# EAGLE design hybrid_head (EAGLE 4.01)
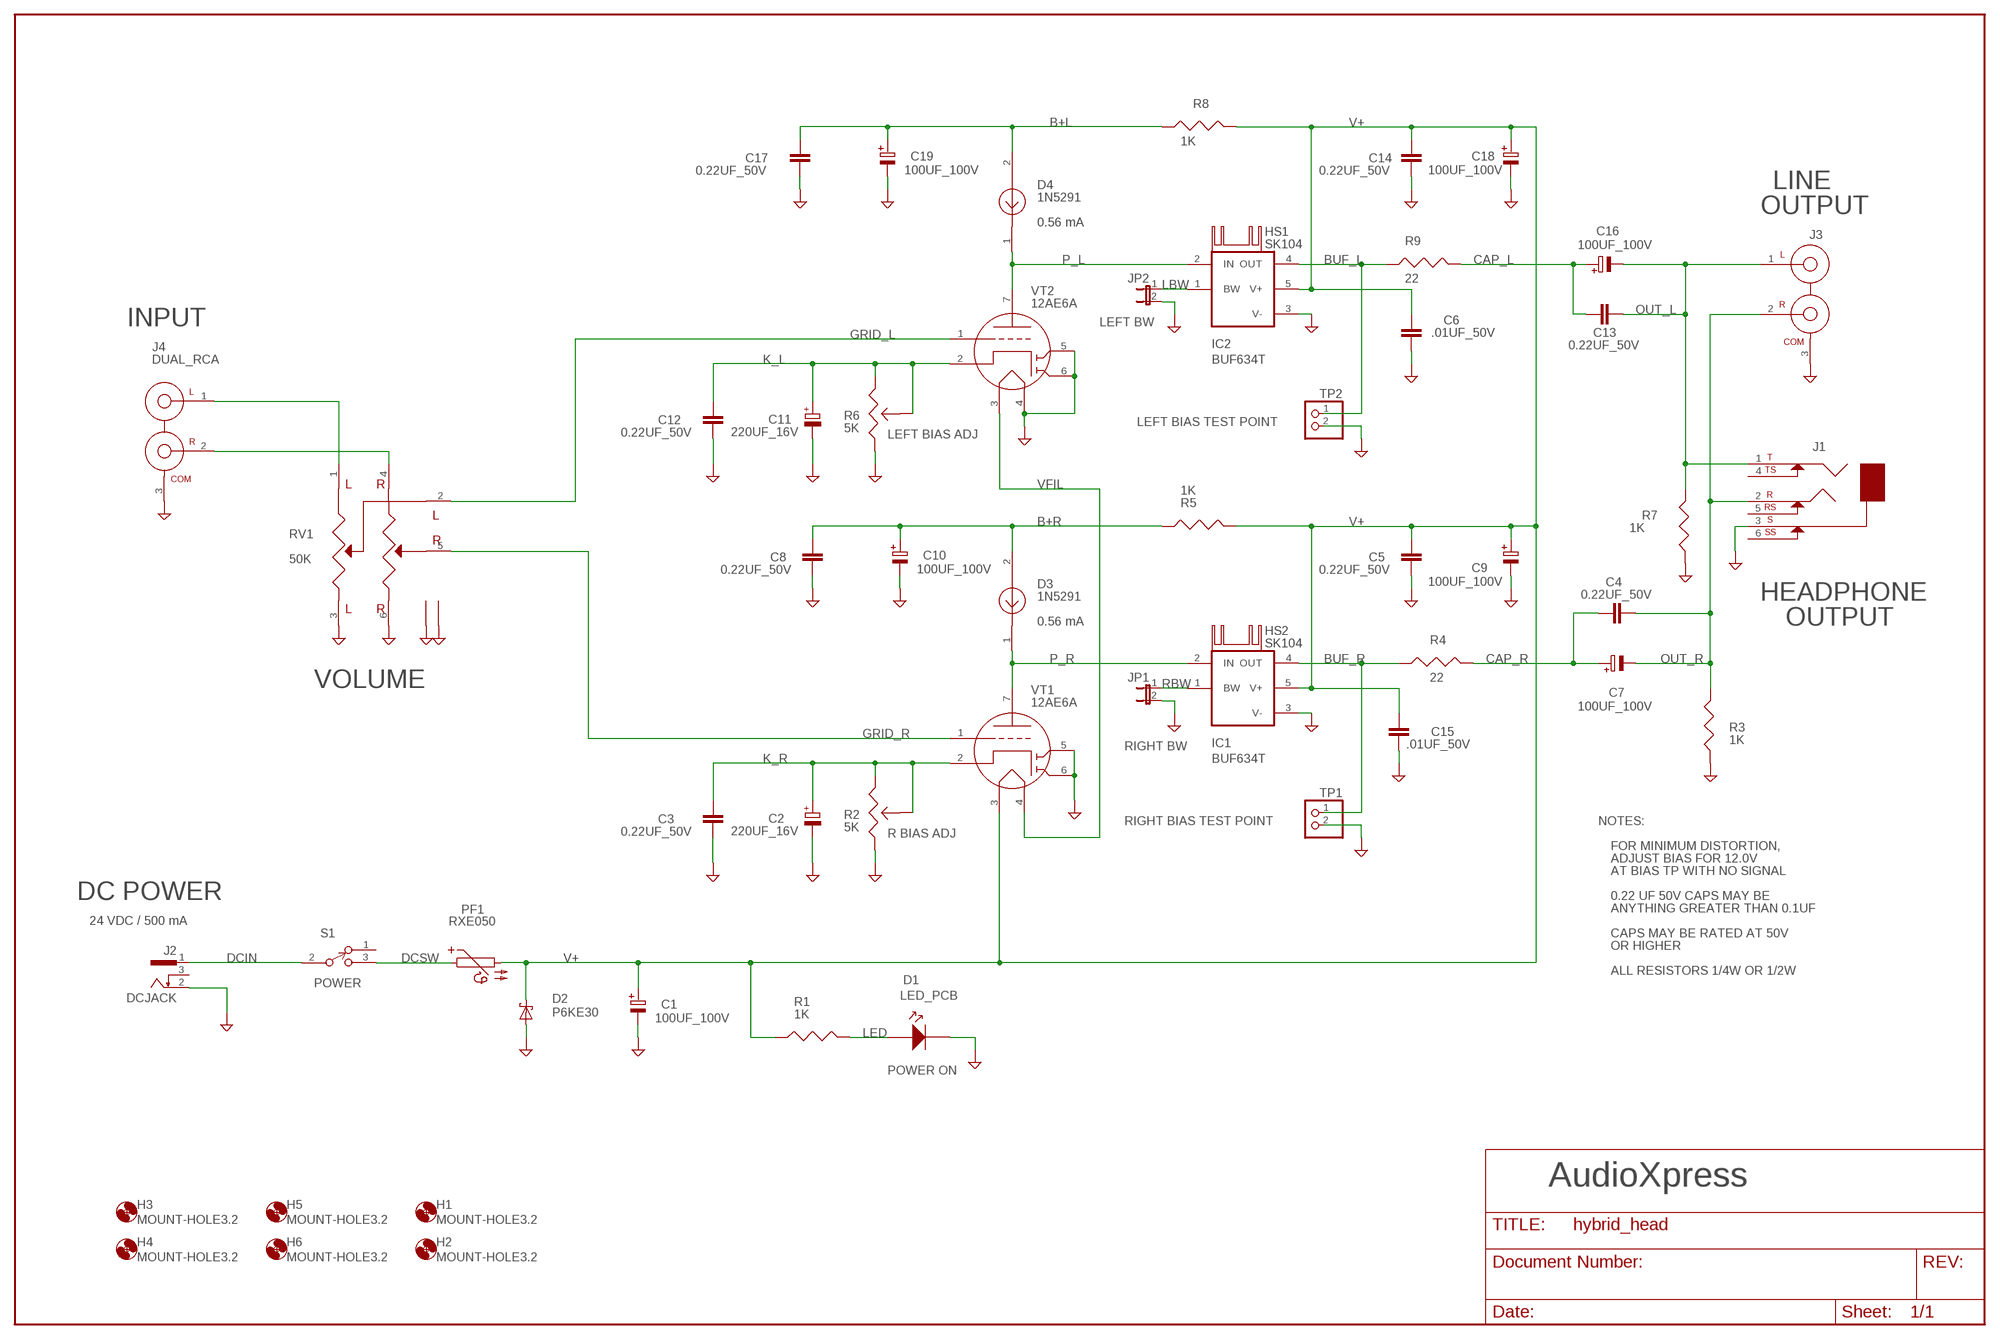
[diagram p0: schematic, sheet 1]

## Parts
C1  100UF_100V  E7,5-16  [E7,5-16]
C2  220UF_16V  CPOL-EUE5-10.5  [E5-10,5]
C3  0.22UF_50V  C-EU150-072X183  [C150-072X183]
C4  0.22UF_50V  C-EU150-072X183  [C150-072X183]
C5  0.22UF_50V  C-EU150-072X183  [C150-072X183]
C6  .01UF_50V  C-EU075-032X103  [C075-032X103]
C7  100UF_100V  E7,5-16  [E7,5-16]
C8  0.22UF_50V  C-EU150-072X183  [C150-072X183]
C9  100UF_100V  E7,5-16  [E7,5-16]
C10  100UF_100V  E7,5-16  [E7,5-16]
C11  220UF_16V  CPOL-EUE5-10.5  [E5-10,5]
C12  0.22UF_50V  C-EU150-072X183  [C150-072X183]
C13  0.22UF_50V  C-EU150-072X183  [C150-072X183]
C14  0.22UF_50V  C-EU150-072X183  [C150-072X183]
C15  .01UF_50V  C-EU075-032X103  [C075-032X103]
C16  100UF_100V  E7,5-16  [E7,5-16]
C17  0.22UF_50V  C-EU150-072X183  [C150-072X183]
C18  100UF_100V  E7,5-16  [E7,5-16]
C19  100UF_100V  E7,5-16  [E7,5-16]
D1  LED_PCB  HLMP-K101  [HLMP-K101]
D2  P6KE30  P6KEXX  [CB417-15]
D3  1N5291  [DO35]
D4  1N5291  [DO35]
H1  MOUNT-HOLE3.2  [3,2]
H2  MOUNT-HOLE3.2  [3,2]
H3  MOUNT-HOLE3.2  [3,2]
H4  MOUNT-HOLE3.2  [3,2]
H5  MOUNT-HOLE3.2  [3,2]
H6  MOUNT-HOLE3.2  [3,2]
HS1  SK104  [SK104]
HS2  SK104  [SK104]
IC1  BUF634T  BUF634TSTAG  [TO-220/5B]
IC2  BUF634T  BUF634TSTAG  [TO-220/5B]
J1  JACK_PHONE  [JACK_PHONE]
J2  DCJACK  [DCJACK]
J3  JACK_DUAL_RCA  [JACK_DUAL_RCA]
J4  DUAL_RCA  JACK_DUAL_RCA  [JACK_DUAL_RCA]
JP1  JP1E  [JP1]
JP2  JP1E  [JP1]
PF1  RXE050  [RXE050]
R1  1K  R1/2W  [R1/2W]
R2  5K  TRIMPOT_3266  [TRIMPOT_3266]
R3  1K  R1/2W  [R1/2W]
R4  22  R1/2W  [R1/2W]
R5  1K  R1/2W  [R1/2W]
R6  5K  TRIMPOT_3266  [TRIMPOT_3266]
R7  1K  R1/2W  [R1/2W]
R8  1K  R1/2W  [R1/2W]
R9  22  R1/2W  [R1/2W]
RV1  50K  POT_EVJC  [POT_EVJC]
S1  SW_SPDT_7101  [SW_SPDT_7101]
TP1  PINHD-1X2  [1X02]
TP2  PINHD-1X2  [1X02]
VT1  12AE6A  TRIODE_7BT  [MINI7_PCB]
VT2  12AE6A  TRIODE_7BT  [MINI7_PCB]

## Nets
B+L: C17.2 C19.+ D4.2 R8.P$1
B+R: C8.2 C10.+ D3.2 R5.P$1
BUF_L: IC2.4(OUT) R9.P$1 TP2.1
BUF_R: IC1.4(OUT) R4.P$1 TP1.1
CAP_L: C13.2 C16.+ R9.P$2
CAP_R: C4.2 C7.+ R4.P$2
DCIN: J2.1 S1.2
DCSW: PF1.P$1 S1.3
GND: C1.- C2.- C3.1 C5.1 C6.1 C8.1 C9.- C10.- C11.- C12.1 C14.1 C15.1 C17.1 C18.- C19.- D1.K D2.A IC1.3(V-) IC2.3(V-) J1.3 J2.2 J3.3 J4.3 JP1.2 JP2.2 R2.1 R3.P$1 R6.1 R7.P$1 RV1.3 RV1.6 RV1.M1 RV1.M2 TP1.2 TP2.2 VT1.5 VT1.6 VT2.4 VT2.5 VT2.6
GRID_L: RV1.2 VT2.1
GRID_R: RV1.5 VT1.1
IN_L: J4.1 RV1.1
IN_R: J4.2 RV1.4
K_L: C11.+ C12.2 R6.2 R6.3 VT2.2
K_R: C2.+ C3.2 R2.2 R2.3 VT1.2
LBW: IC2.1(BW) JP2.1
LED: D1.A R1.P$2
OUT_L: C13.1 C16.- J1.1 J3.1 R7.P$2
OUT_R: C4.1 C7.- J1.2 J3.2 R3.P$2
P_L: D4.1 IC2.2(IN) VT2.7
P_R: D3.1 IC1.2(IN) VT1.7
RBW: IC1.1(BW) JP1.1
V+: C1.+ C5.2 C6.2 C9.+ C14.2 C15.2 C18.+ D2.K(C) IC1.5(V+) IC2.5(V+) PF1.P$2 R1.P$1 R5.P$2 R8.P$2 VT1.3
VFIL: VT1.4 VT2.3
Unconnected: J1.4 J1.5 J1.6 J2.3 S1.1

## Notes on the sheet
- LINE
- OUTPUT
- 0.56 mA
- INPUT | LEFT BW
- LEFT BIAS TEST POINT
- LEFT BIAS ADJ
- HEADPHONE
- 0.56 mA | OUTPUT
- VOLUME
- RIGHT BW
- RIGHT BIAS TEST POINT | NOTES:
- R BIAS ADJ
- FOR MINIMUM DISTORTION,
- ADJUST BIAS FOR 12.0V
- AT BIAS TP WITH NO SIGNAL
- DC POWER | 0.22 UF 50V CAPS MAY BE
- ANYTHING GREATER THAN 0.1UF
- 24 VDC / 500 mA
- CAPS MAY BE RATED AT 50V
- OR HIGHER
- ALL RESISTORS 1/4W OR 1/2W
- POWER
- POWER ON
- AudioXpress

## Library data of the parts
C1 C7 C9 C10 C16 C18 C19 = polcap:E7,5-16
C2 C11 = rcl:CPOL-EU: POLARIZED CAPACITOR, European symbol
C3-C6 C8 C12-C15 C17 = rcl:C-EU: CAPACITOR, European symbol
D1 = wheat:HLMP-K101: LED, T-1 (3MM) PCB
D2 = diode:P6KEXX: DIODE
D3 D4 = wheat:1N5291: DIODE, CURRENT REGULATOR, 1N5291
H1-H6 = holes:MOUNT-HOLE: MOUNTING HOLE with drill center marker
HS1 HS2 = heatsink:SK104: HEATSINK
IC1 IC2 = burr-brown:BUF634T: BURR-BROWN
J1 = wheat:JACK_PHONE: JACK, PHONE, 1/4" STEREO W/SW REAN
J2 = wheat:DCJACK: DC POWER JACK, 2.5mm/5.5mm CUI-STACK PJ-102B
J3 J4 = wheat:JACK_DUAL_RCA: JACK, DUAL RCA, VERTICAL CONNECT-TECH CTP2-208
JP1 JP2 = jumper:JP1E: JUMPER
PF1 = wheat:RXE050: POLYFUSE, RXE050
R1 R3-R5 R7-R9 = wheat:R1/2W: RESISTOR, 1/2W THM
R2 R6 = wheat:TRIMPOT_3266: TRIM POT, 1/4" BOURNS 3266
RV1 = wheat:POT_EVJC: POT, DUAL, EVJC PANASONIC
S1 = wheat:SW_SPDT_7101: SWITCH, SPDT TOGGLE, C&K 7101
TP1 TP2 = pinhead:PINHD-1X2: PIN HEADER
VT1 VT2 = wheat:TRIODE_7BT: TRIODE W/ 2 DIODES, 7-PIN MINI, 7BT

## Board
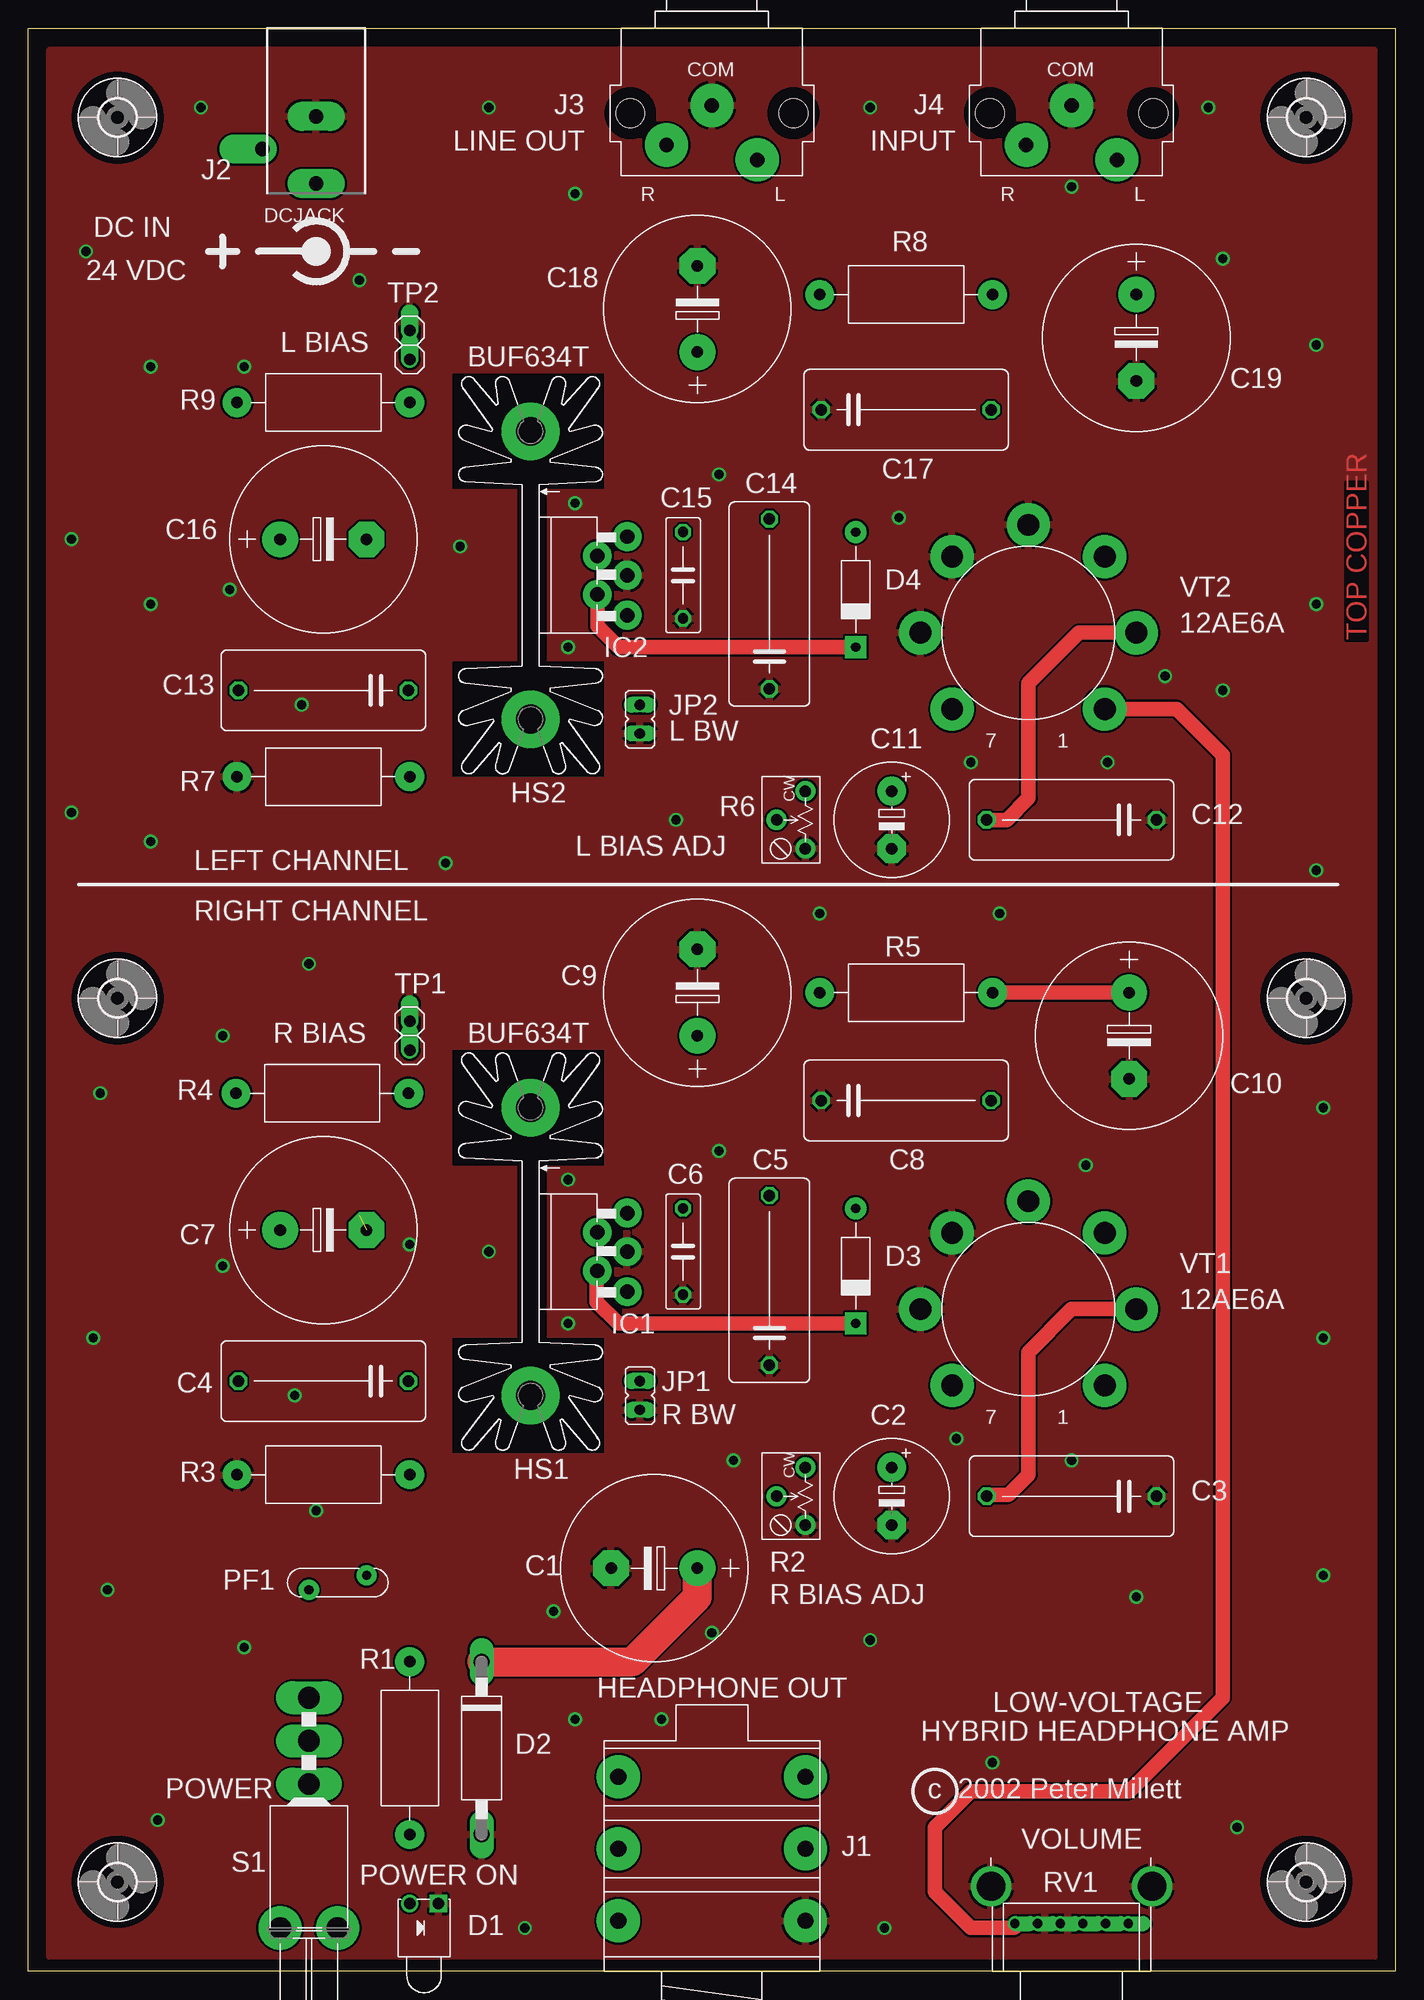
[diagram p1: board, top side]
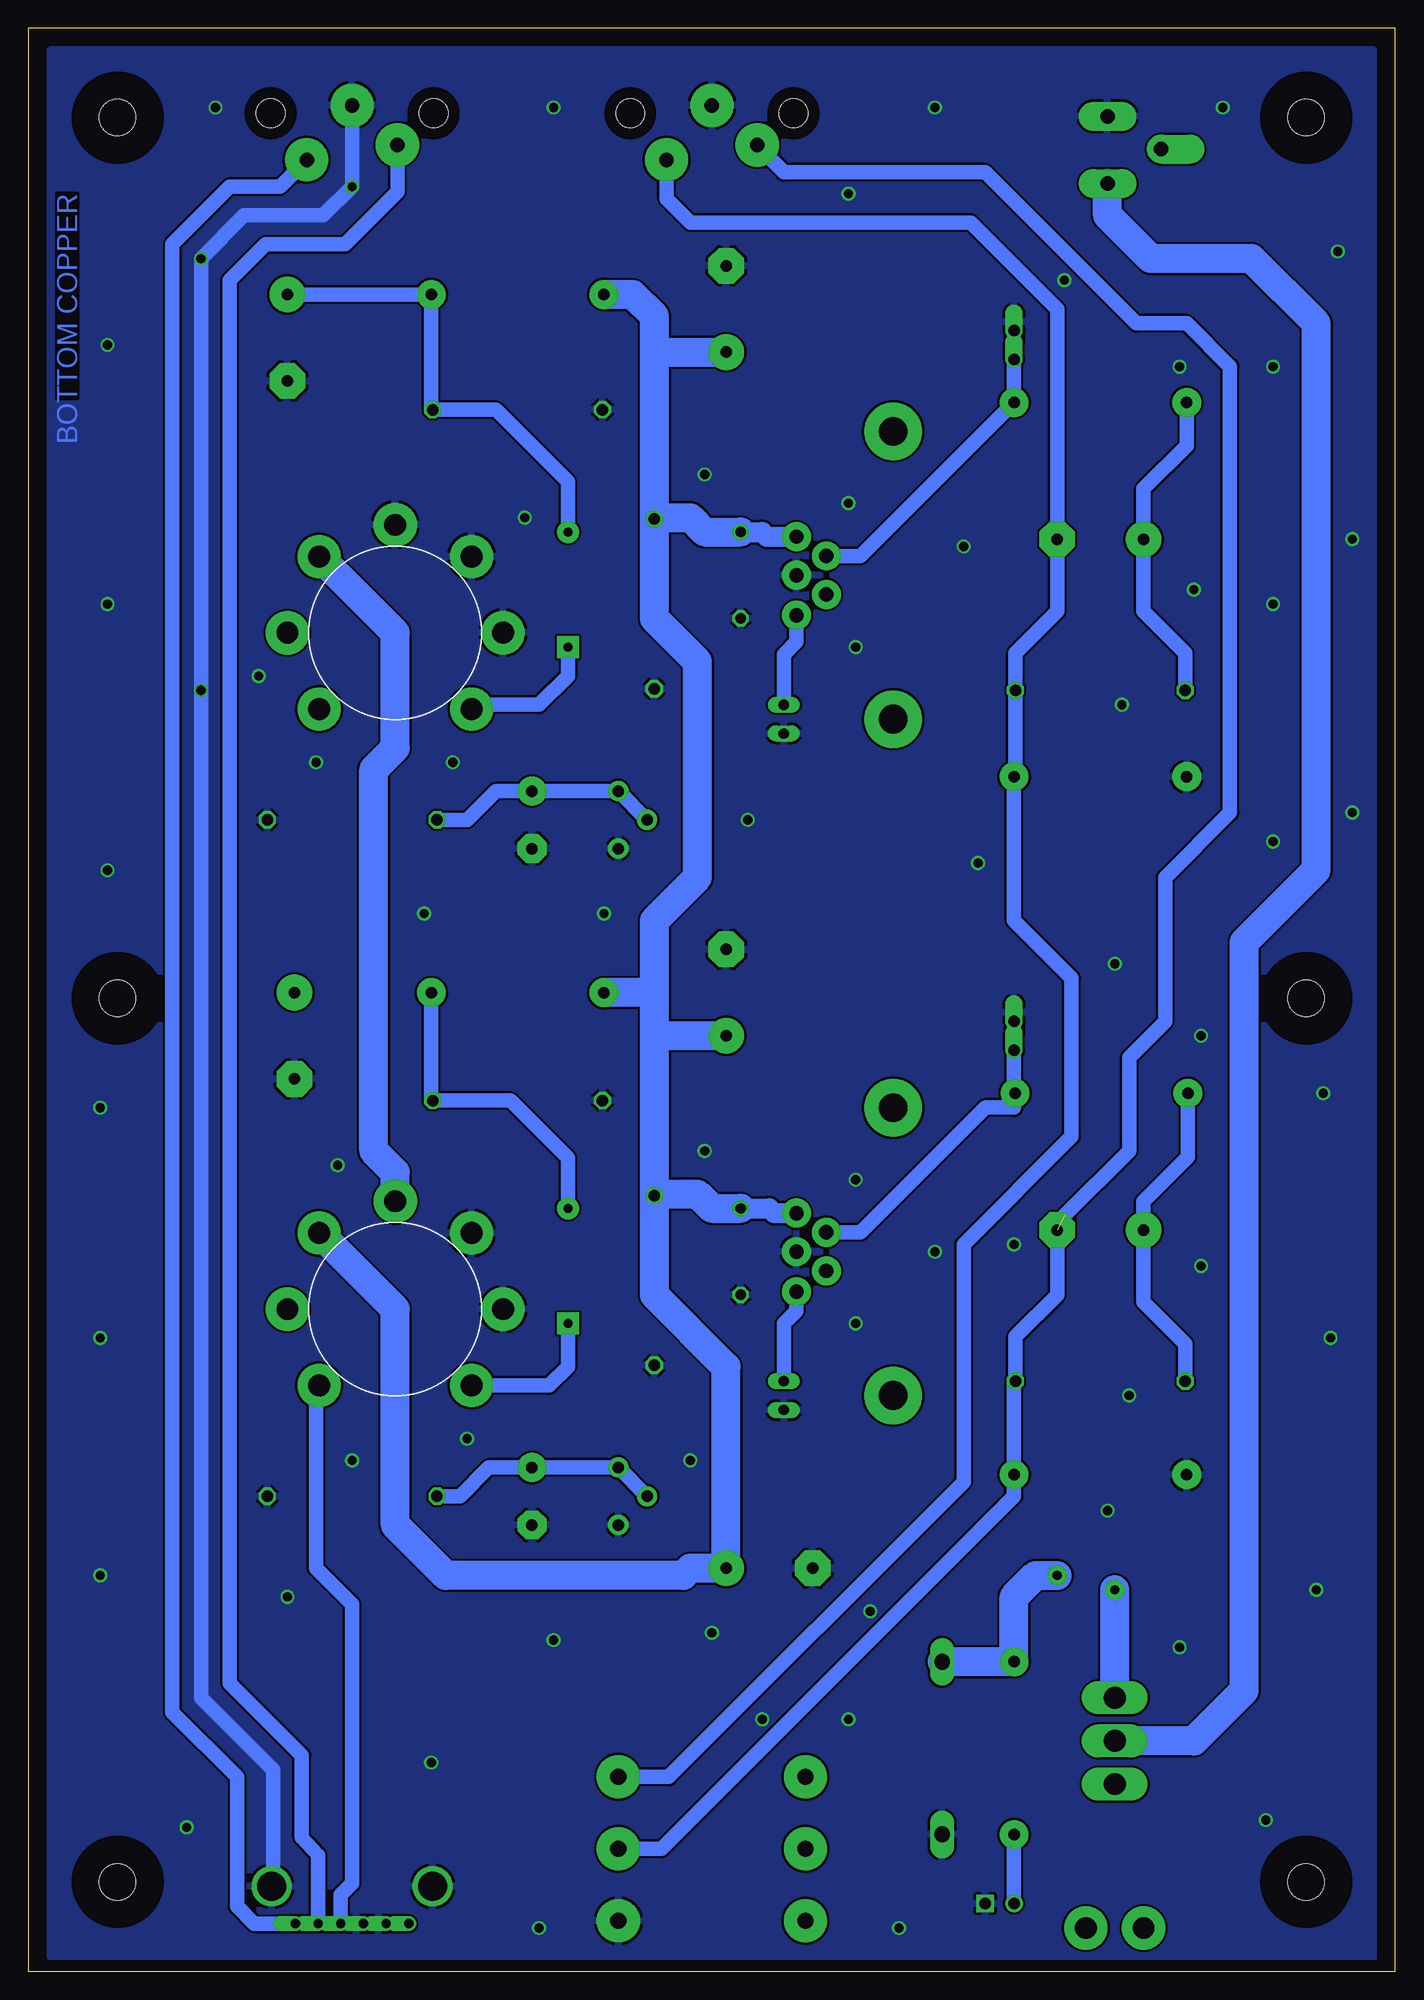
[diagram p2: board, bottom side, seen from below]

Size 120.65 x 171.45 mm. Coordinates in mm from the lower left corner, seen from the top.
Outline: 0,171.45 120.65,171.45 120.65,0 0,0 0,171.45
Copper layers used: Top, Bottom

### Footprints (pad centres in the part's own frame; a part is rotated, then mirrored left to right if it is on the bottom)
E7,5-16 = drill 1.016 pad 3.15 round: + -3.81,0 | drill 1.016 pad 3.15 octagon: - 3.81,0
E5-10,5 = drill 1.016 pad 2.54 round: + -2.54,0 | drill 1.016 pad 2.54 octagon: - 2.54,0
C150-072X183 = drill 1.016 octagon: 1 -7.493,0; 2 7.493,0
C075-032X103 = drill 0.914 octagon: 1 -3.81,0; 2 3.81,0
HLMP-K101 = drill 1.016 round: A -1.27,4.699 | drill 1.016 square: K 1.27,4.699
CB417-15 = drill 1.397 long: A 7.62,0; K -7.62,0
DO35 = drill 0.813 pad 1.93 square: 1 -5.08,0 | drill 0.813 pad 1.93 round: 2 5.08,0
3,2 = hole 3.2: 0,0
SK104 = drill 2.54 pad 5.08 round: A2,5 -12.7,-0.762; B2,5 12.7,-0.762
TO-220/5B = drill 1.27 pad 2.54 round: 1 -3.531,-7.772; 2 -1.702,-5.131; 3 0,-7.772; 4 1.702,-5.131; 5 3.404,-7.772
JACK_PHONE = drill 1.422 pad 3.81 round: 1 8.255,17.145; 2 8.255,10.795; 3 8.255,4.445; 4 -8.255,17.145; 5 -8.255,10.795; 6 -8.255,4.445
DCJACK = drill 1.27 pad 2.54 long: 1 0,13.694; 2 0,7.778 | drill 1.27 pad 2.54 offset: 3 4.732,10.659
JACK_DUAL_RCA = drill 1.27 pad 3.81 round: 1 -4,11.6; 2 4,10.3; 3 0,6.8 | hole 2.54: -7.2,7.5; 7.2,7.5
JP1 = drill 0.914 long: 1 0,-1.27; 2 0,1.27
RXE050 = drill 0.813 pad 1.778 round: P$1 -0.635,2.54; P$2 0.635,-2.54
R1/2W = drill 1.016 pad 2.54 round: P$1 0,0; P$2 15.24,0
TRIMPOT_3266 = drill 1.016 pad 1.778 round: 1 -2.54,-1.27; 2 0,1.27; 3 2.54,-1.27
POT_EVJC = drill 0.813 offset: 1 5,4.2; 2 -5,4.2; 3 -3,4.2; 4 3,4.2; 5 1,4.2; 6 -1,4.2 | drill 2.54 round: M1 -7.1,7.5; M2 7.1,7.5
SW_SPDT_7101 = drill 1.93 long: 1 0,12.7; 2 0,16.51; 3 0,20.32 | drill 1.93 pad 3.81 round: B -2.54,0; B1 2.54,0
1X02 = drill 1.016 offset: 1 -1.27,0; 2 1.27,0
MINI7_PCB = drill 1.93 pad 3.81 round: 1 6.731,-6.731; 2 9.525,0; 3 6.731,6.731; 4 0,9.525; 5 -6.731,6.731; 6 -9.525,0; 7 -6.731,-6.731

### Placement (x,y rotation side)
C1  55.24,35.56 180 top
C2  76.2,41.91 270 top
C3  92.08,41.91 180 top
C4  26.04,52.07 180 top
C5  65.41,60.96 90 top
C6  57.78,63.5 90 top
C7  26.04,65.41 0 top
C8  77.47,76.83 0 top
C9  59.05,86.36 90 top
C10  97.16,82.55 270 top
C11  76.2,101.6 270 top
C12  92.08,101.6 180 top
C13  26.04,113.03 180 top
C14  65.41,120.65 90 top
C15  57.78,123.19 90 top
C16  26.04,126.36 0 top
C17  77.47,137.79 0 top
C18  59.05,146.69 90 top
C19  97.79,144.15 270 top
D1  34.92,1.27 0 top
D2  40.01,19.68 270 top
D3  73.03,62.23 90 top
D4  73.03,121.92 90 top
H1  7.87,7.87 0 top
H2  112.78,7.87 0 top
H3  7.87,85.85 0 top
H4  112.78,85.85 0 top
H5  7.87,163.58 0 top
H6  112.78,163.58 0 top
HS1  45.09,63.5 270 top
HS2  45.09,123.19 270 top
IC1  45.09,63.5 90 top
IC2  45.09,123.19 90 top
J1  60.33,0 0 top
J2  25.4,171.45 180 top
J3  60.33,171.45 180 top
J4  92.08,171.45 180 top
JP1  53.98,50.8 180 top
JP2  53.98,110.49 180 top
PF1  27.3,34.29 90 top
R1  33.66,27.3 270 top
R2  67.31,41.91 90 top
R3  18.41,43.81 0 top
R4  33.55,77.47 180 top
R5  85.09,86.36 180 top
R6  67.31,101.6 90 top
R7  18.41,105.41 0 top
R8  85.09,147.96 180 top
R9  33.66,138.43 180 top
RV1  92.08,0 0 top
S1  24.77,3.81 0 top
TP1  33.66,82.55 90 top
TP2  33.66,143.51 90 top
VT1  88.27,58.42 0 top
VT2  88.27,118.11 0 top

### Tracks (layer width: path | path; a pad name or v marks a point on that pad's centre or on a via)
B+L
  Bottom 1.27: D4.2 73.03,131.44 79.38,137.79 C17.2 85.09,137.79 R8.P$1 C19.+
B+R
  Top 1.27: R5.P$1 C10.+
  Bottom 1.27: D3.2 73.03,71.75 78.11,76.83 C8.2 85.09,76.83 R5.P$1
BUF_L
  Bottom 1.27: IC2.4 47.19,124.89 R9.P$1 TP2.1
BUF_R
  Bottom 1.27: IC1.4 47.19,65.2 36.2,76.2 33.66,76.2 | R4.P$1 33.66,76.2 | 33.66,76.2 TP1.1
CAP_L
  Bottom 1.27: R9.P$2 18.41,134.62 22.23,130.81 C16.+ 22.23,120.02 18.54,116.33 C13.2
CAP_R
  Bottom 1.27: R4.P$2 18.31,71.86 22.23,67.94 C7.+ 22.23,59.05 18.54,55.37 C4.2
DCIN
  Bottom 2.54: J2.1 25.4,154.94 21.59,151.13 12.7,151.13 6.99,145.41 6.99,97.16 13.34,90.81 13.34,24.77 17.78,20.32 S1.2
DCSW
  Bottom 2.54: S1.3 PF1.P$1
GND  (via drill 0.81)
  Bottom 1.27: J4.3 v92.08,157.48 94.61,154.94 101.6,154.94 v105.41,151.13 v105.41,113.03 105.41,24.13 99.06,17.78 99.06,8.26 99.17,8.14 RV1.M2
  other vias: 106.68,12.7 97.79,33.02 74.3,29.21 92.08,45.09 11.43,13.34 19.05,28.57 25.4,40.64 23.5,50.8 10.79,99.69 5.71,55.88 6.99,33.66 24.77,88.9 36.83,97.79 33.66,64.14 17.14,62.23 40.64,63.5 69.85,93.34 62.23,45.09 114.3,34.92 114.3,55.88 113.67,97.16 60.96,72.39 43.81,3.81 75.56,3.81 40.64,164.47 74.3,164.47 104.14,164.47 113.67,143.51 113.67,120.65 15.24,164.47 10.79,141.6 10.79,120.65 19.05,141.6 17.78,121.92 38.1,125.73 48.26,129.54 47.62,116.84 60.96,132.08 81.92,46.99 76.83,128.27 85.09,18.41 83.19,106.68 95.25,106.68 100.33,114.3 93.34,71.12 85.72,93.34 57.15,101.6 47.62,69.85 47.62,57.15 55.88,22.23 6.35,77.47 114.3,76.2 48.26,22.23 60.33,29.84 5.08,151.76 3.81,126.36 3.81,102.23 17.14,82.55 29.21,149.22 48.26,156.84 24.13,111.76 46.35,31.75
  pour Top: 1.91,169.54 118.75,169.54 118.75,1.27 1.91,1.27
  pour Bottom: 118.75,1.27 1.91,1.27 1.91,169.54 118.75,169.54
GRID_L
  Top 1.27: VT2.1 101.35,111.38 105.41,107.31 105.41,24.13 97.16,15.88 83.19,15.88 80.01,12.7 80.01,6.99 83.19,3.81 87,3.81 87.08,3.89 RV1.2
GRID_R
  Bottom 1.27: RV1.5 93.09,6.73 93.08,6.73 92.08,7.74 92.08,32.38 95.25,35.56 95.25,51.44 VT1.1
IN_L
  Bottom 1.27: RV1.1 100.72,4.2 102.23,5.71 102.23,17.14 107.95,22.86 107.95,152.4 102.87,157.48 98.42,157.48 97.16,158.75 95.72,159.85 J4.1
IN_R
  Bottom 1.27: J4.2 88.08,157.03 92.71,152.4 99.69,152.4 102.87,149.22 102.87,25.4 96.52,19.05 96.52,11.81 95.08,10.24 RV1.4
K_L
  Top 1.27: VT2.2 92.71,118.11 88.27,113.67 88.27,103.5 86.36,101.6 C12.2
  Bottom 1.27: C12.2 81.92,101.6 79.38,104.14 C11.+ R6.3 R6.2
K_R
  Top 1.27: VT1.2 92.08,58.42 88.27,54.61 88.27,43.81 86.49,42.04 84.58,42.04 84.45,41.91 C3.2
  Bottom 1.27: C3.2 82.55,41.91 80.01,44.45 C2.+ R2.3 R2.2
LBW
  Bottom 1.27: IC2.1 52.86,117.32 53.98,116.2 JP2.1
LED
  Bottom 1.27: D1.A R1.P$2
OUT_L
  Bottom 1.27: J1.1 64.14,17.14 38.1,43.18 38.1,64.14 28.57,73.66 28.57,87.63 33.66,92.71 R7.P$2 33.53,105.54 C13.1 33.53,116.33 29.84,120.02 C16.- 29.84,146.69 37.47,154.31 62.23,154.31 64.33,156.4 J3.1
OUT_R  (1 unrouted)
  Bottom 1.27: J1.2 64.77,10.79 33.66,41.91 R3.P$2 33.66,52.07 C4.1 33.53,56.01 29.84,59.69 C7.- | J3.2 56.33,161.1 53.98,158.75 36.2,158.75 22.86,145.41 18.41,145.41 14.61,141.6 14.61,102.23 20.32,96.52 20.32,83.82 23.5,80.64 23.5,72.39 29.21,66.67
P_L
  Top 1.27: IC2.2 50.22,118.69 52.07,116.84 D4.1
  Bottom 1.27: VT2.7 81.28,111.38 81.28,111.76 75.56,111.76 73.03,114.3 D4.1
P_R
  Top 1.27: D3.1 52.07,57.15 50.16,59.05 50.16,61.59 50.22,61.65 IC1.2
  Bottom 1.27: 80.9,51.69 VT1.7 | 80.9,51.69 80.64,51.44 | 80.9,51.69 74.68,51.69 73.03,53.34 D3.1
RBW
  Bottom 1.27: IC1.1 52.86,58.27 53.98,57.15 JP1.1
V+
  Top 2.54: C1.+ 59.05,33.02 53.34,27.3 D2.K
  Bottom 1.778: IC1.5 54.84,66.9 55.24,67.31 C6.2 | IC2.5 55.47,126.59 55.88,127 C15.2
  Bottom 2.54: PF1.P$2 31.75,34.92 33.66,33.02 R1.P$1 D2.K | C6.2 60.33,67.31 61.59,68.58 65.41,68.58 | 65.41,68.58 C5.2 65.41,59.69 59.05,53.34 C1.+ 62.23,35.56 62.87,34.92 83.82,34.92 88.27,39.37 88.27,58.42 VT1.3 | 65.41,68.58 65.41,82.55 | C15.2 60.96,127 62.23,128.27 64.77,128.27 64.9,128.14 C14.2 | C14.2 65.41,119.38 61.59,115.57 61.59,96.52 65.41,92.71 65.41,82.55 | R5.P$2 65.41,86.36 65.41,82.55 | 65.41,82.55 C9.+ | C14.2 65.41,142.88 | R8.P$2 67.31,147.96 65.41,146.05 65.41,142.88 | 65.41,142.88 C18.+
VFIL
  Bottom 2.54: VT2.3 88.27,118.11 88.27,107.95 90.17,106.05 90.17,72.39 88.27,70.48 VT1.4

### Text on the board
Top: TOP COPPER
Bottom: BOTTOM COPPER
tPlace: INPUT | DC IN | 24 VDC | L BIAS | BUF634T | 12AE6A | L BW | L BIAS ADJ | LEFT CHANNEL | RIGHT CHANNEL | R BIAS | BUF634T | 12AE6A | R BW | R BIAS ADJ | HEADPHONE OUT | LOW-VOLTAGE | HYBRID HEADPHONE AMP | POWER | c 2002 Peter Millett | VOLUME | POWER ON
tNames: LINE OUT
Document: 2.375 CL | 3.625 CL | 1.00 CL | 6.75 | 6.44 | 3.38 | 0.31 | 0.00 | 0.00 | 0.31 | 4.44 | 4.75 | 3.625 CL | 1.375 CL | 2.375 CL | 0.975 CL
